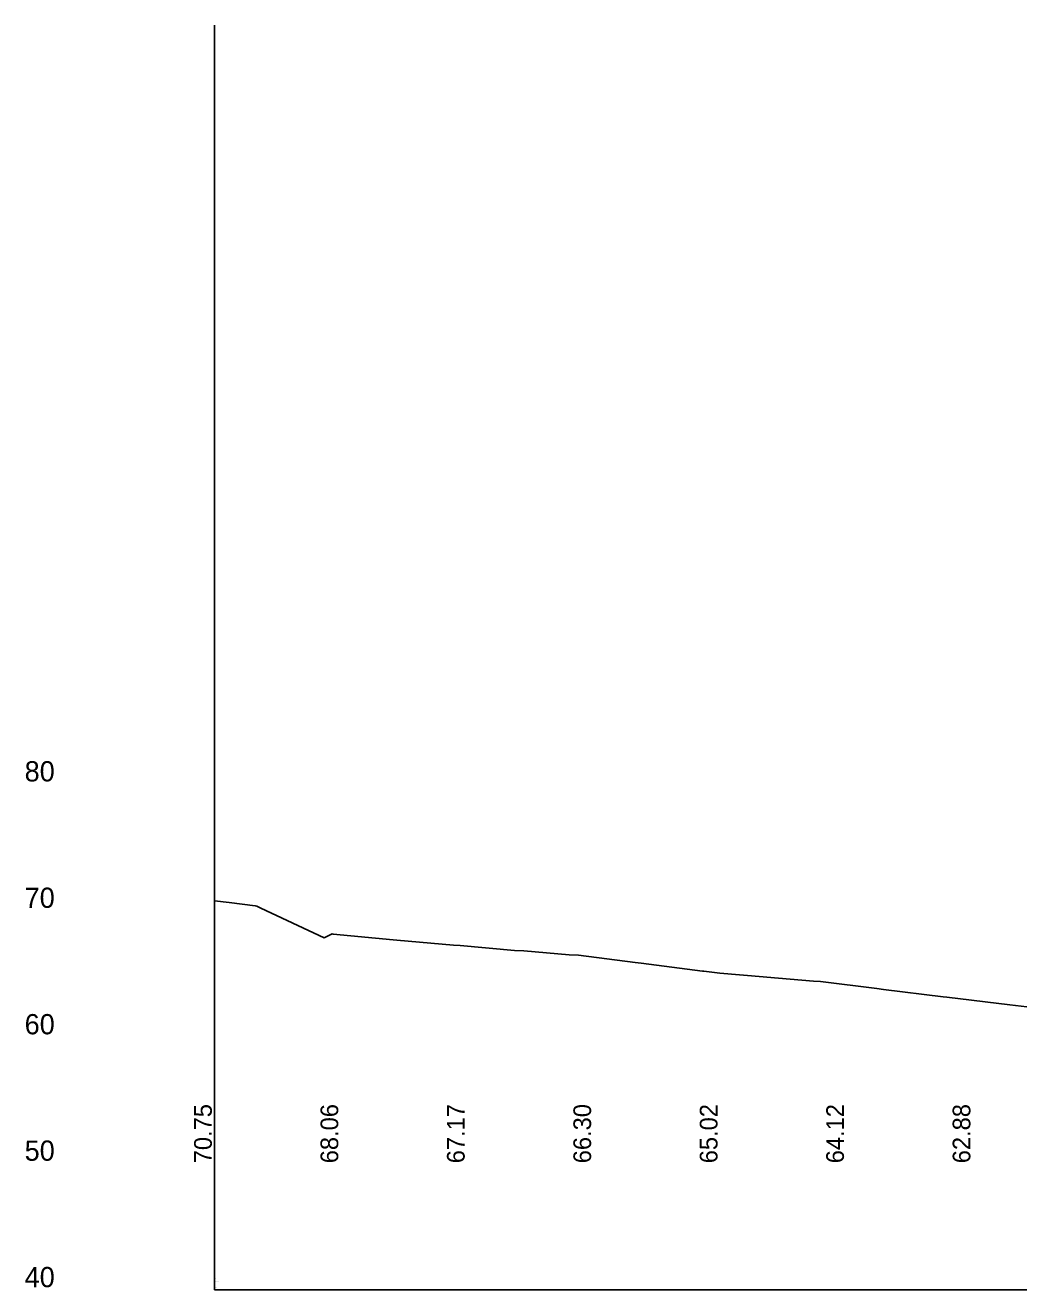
# Model space of a CAD drawing. Extents: x 2526761 to 2530854, y 882903 to 888012.
# Drawn here: x 2526764 to 2527160, y 884062 to 884562 of the extents above; entities that cross this region are included whole.
import ezdxf

# ---------------------------------------------------------------- set-up
doc = ezdxf.new("R2010")
doc.units = 0
for name, color, linetype in [('RD_DDB_ElevTX', 7, 'Continuous'), ('RD_DDB_Profile_EX', 7, 'Continuous'), ('RD_DDB_StripGrade', 7, 'Continuous'), ('RD_GPK_Profile_Cell', 7, 'Continuous')]:
    doc.layers.add(name, color=color, linetype=linetype)

msp = doc.modelspace()

# ---------------------------------------------------------------- linework, layer by layer
at = {"layer": 'RD_DDB_Profile_EX'}
msp.add_lwpolyline([(2526838.95, 884215.85), (2526844.79, 884215.16), (2526855.12, 884213.93), (2526855.73, 884213.74), (2526857.31, 884212.93), (2526882.44, 884201.26), (2526885.52, 884202.85), (2526886, 884202.67), (2526909.61, 884200.41), (2526911.13, 884200.35), (2526933.55, 884198.28), (2526936.23, 884198.17), (2526957.71, 884196.24), (2526961.31, 884196.07), (2526979.22, 884194.5), (2526982.97, 884194.32), (2527005.32, 884191.48), (2527007.76, 884191.22), (2527031.95, 884188.09), (2527032.51, 884188.04), (2527038.84, 884187.2), (2527056.01, 884185.77), (2527057.46, 884185.66), (2527075.92, 884184.14), (2527078.66, 884183.95), (2527101, 884181.2), (2527103.64, 884180.79), (2527127.24, 884177.93), (2527128.62, 884177.71), (2527153.61, 884174.71), (2527160.23, 884173.92)], dxfattribs=at)
at = {"layer": 'RD_GPK_Profile_Cell'}
for q in [(2526838.95, 884562.08), (2527160.24, 884062.08), (2526838.95, 884062.08)]:
    msp.add_line((2526838.95, 884062.08), q, dxfattribs=at)

# ---------------------------------------------------------------- texts
at = {"layer": 'RD_DDB_ElevTX'}
for s, p in [('80', (2526763.93, 884263.08)), ('70', (2526763.93, 884213.08)), ('60', (2526763.93, 884163.08)), ('50', (2526763.93, 884113.08)), ('40', (2526763.93, 884063.08))]:
    msp.add_text(s, height=8, dxfattribs=at).set_placement(p)
at = {"layer": 'RD_DDB_StripGrade'}
for s, p in [('70.75', (2526837.95, 884112.08)), ('68.06', (2526887.95, 884112.08)), ('67.17', (2526937.95, 884112.08)), ('66.30', (2526987.95, 884112.08)), ('65.02', (2527037.95, 884112.08)), ('64.12', (2527087.95, 884112.08)), ('62.88', (2527137.95, 884112.08))]:
    msp.add_text(s, height=7, rotation=90, dxfattribs=at).set_placement(p)
at = {"layer": 'RD_GPK_Profile_Cell'}
for s, height, p in [('059', 0.208, (2526838.95, 884066.46)), ('OFD1', 0.208, (2526838.95, 884065.83)), ('1000.000000', 0.2083, (2526838.95, 884065.21)), ('40', 0.208, (2526838.95, 884064.58)), ('50', 0.208, (2526838.95, 884063.96)), ('10', 0.208, (2526838.95, 884063.33)), ('NOGAP', 0.208, (2526838.95, 884062.71))]:
    msp.add_text(s, height=height, dxfattribs=at).set_placement(p)

doc.saveas('drawing.dxf')
